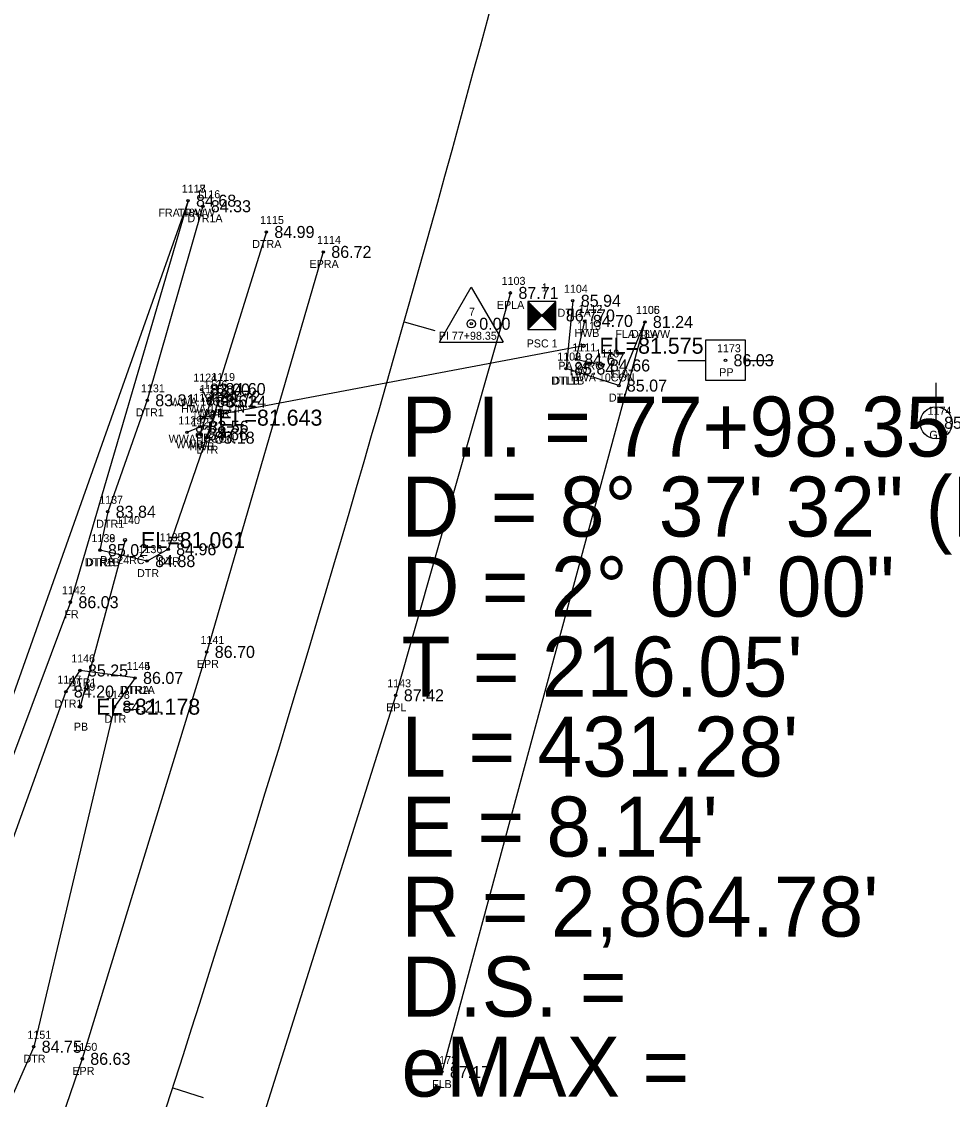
# Model space of a CAD drawing. Extents: x 2139392 to 2143384, y 505395 to 510520.
# Drawn here: x 2141351.5 to 2141467.9, y 510187.6 to 510322.4 of the extents above; entities that cross this region are included whole.
import ezdxf

# ---------------------------------------------------------------- set-up
doc = ezdxf.new("R2010")
doc.units = 0
for name, color, linetype in [('RD_EX_Bridge', 7, 'Continuous'), ('RD_EX_Bridge_txCode', 7, 'Continuous'), ('RD_EX_DR_Pipe', 7, 'Continuous'), ('RD_EX_DR_Pipe_txCode', 7, 'Continuous'), ('RD_EX_Fence_Other', 7, 'Continuous'), ('RD_EX_Fence_Other_txCode', 7, 'Continuous'), ('RD_EX_H2O', 7, 'Continuous'), ('RD_EX_H2O_txCode', 7, 'Continuous'), ('RD_EX_Road', 7, 'Continuous'), ('RD_EX_Road_txCode', 7, 'Continuous'), ('RD_EX_TX_Bridge_ELEV', 7, 'Continuous'), ('RD_EX_TX_Fence_Other_ELEV', 7, 'Continuous'), ('RD_EX_TX_H2O_ELEV', 7, 'Continuous'), ('RD_EX_TX_Road_ELEV', 7, 'Continuous'), ('RD_EX_TX_UT_ELEV', 7, 'Continuous'), ('RD_EX_TX_VEG_ELEV', 7, 'Continuous'), ('RD_EX_UT', 7, 'Continuous'), ('RD_EX_UT_txCode', 7, 'Continuous'), ('RD_EX_VEG', 7, 'Continuous'), ('RD_EX_VEG_txCode', 7, 'Continuous'), ('RD_HC_Cl', 7, 'Continuous'), ('RD_HC_Data', 7, 'Continuous'), ('RD_HC_Data_Tic', 7, 'Continuous'), ('RD_HC_Survey', 7, 'Continuous'), ('RD_HC_Survey_ELEV', 7, 'Continuous'), ('RD_HC_txCode', 7, 'Continuous'), ('RD_SMD_Locator', 7, 'Continuous'), ('RD_TX_Pipe_ElevEX', 7, 'Continuous')]:
    doc.layers.add(name, color=color, linetype=linetype)

msp = doc.modelspace()

# ---------------------------------------------------------------- linework, layer by layer
at = {"layer": 'RD_EX_Bridge'}
for p, q in [((2141374.04, 510276.37), (2141374.82, 510274.93)), ((2141375.34, 510275.48), (2141373.79, 510270.78)), ((2141373.87, 510271.73), (2141372.18, 510271.02))]:
    msp.add_line(p, q, dxfattribs=at)
msp.add_lwpolyline([(2141424.06, 510279.39), (2141420.85, 510280.14), (2141421.91, 510284.95)], dxfattribs=at)
at = {"layer": 'RD_EX_DR_Pipe'}
for p, q in [((2141421.74, 510281.85), (2141374.1, 510272.86)), ((2141364.45, 510257.56), (2141358.83, 510236.74))]:
    msp.add_line(p, q, dxfattribs=at)
at = {"layer": 'RD_EX_Fence_Other'}
msp.add_line((2141429.42, 510284.83), (2141404.04, 510191.07), dxfattribs=at)
msp.add_lwpolyline([(2141372.32, 510299.98), (2141357.62, 510249.8), (2141299.84, 510095.47), (2141291.7, 510075.55), (2141249.56, 510057.46), (2141172.32, 510090.13)], dxfattribs=at)
at = {"layer": 'RD_EX_H2O'}
msp.add_line((2141420.41, 510287.47), (2141419.58, 510279), dxfattribs=at)
for points in [[(2141374.17, 510299.29), (2141367.22, 510275.03), (2141362.28, 510261.1), (2141361.31, 510256.3)], [(2141382.11, 510296.07), (2141376, 510276.44), (2141376.07, 510274.88), (2141374.63, 510270.36), (2141369.84, 510256.41), (2141367.21, 510254.93), (2141361.31, 510256.3)], [(2141429.42, 510284.83), (2141426.17, 510276.87), (2141419.58, 510279)], [(2141365.7, 510240.33), (2141358.81, 510241.26), (2141357.05, 510238.63), (2141342.24, 510197.62), (2141327.87, 510160.27)], [(2141365.7, 510240.33), (2141363.12, 510236.72), (2141353.03, 510194.23), (2141336.56, 510156.75), (2141327.87, 510160.27)]]:
    msp.add_lwpolyline(points, dxfattribs=at)
at = {"layer": 'RD_EX_Road'}
for points in [[(2141389.23, 510293.58), (2141374.66, 510243.58), (2141359.1, 510192.72), (2141341.17, 510140.58), (2141322.74, 510087.97), (2141303.61, 510035.12), (2141287.18, 509990.16), (2141276.99, 509962.02), (2141248.91, 509884.35), (2141213.37, 509787.47), (2141207.76, 509772.94), (2141199.35, 509749.36), (2141191.47, 509727.8), (2141175.93, 509686.04), (2141140.09, 509588.3), (2141106.08, 509494.11), (2141096.82, 509469.24), (2141063.82, 509378.98), (2141052.52, 509348.48), (2141043.48, 509323.88)], [(2141412.62, 510288.46), (2141398.29, 510238.16), (2141381.65, 510185.39), (2141379.05, 510176.51), (2141367.08, 510141.57), (2141363.58, 510131.95), (2141345.23, 510080.36), (2141326.05, 510027.03), (2141308.64, 509979.4), (2141271.24, 509876.37), (2141240, 509789.51), (2141233.78, 509773.43), (2141223.56, 509746.41), (2141212.18, 509714.93), (2141204.36, 509694.36), (2141197.99, 509676.56), (2141193.66, 509664.6), (2141161.61, 509577.24), (2141123.75, 509473.61), (2141115.5, 509450.65), (2141102.09, 509414.61), (2141086.27, 509371.27), (2141050.42, 509272.83)]]:
    msp.add_lwpolyline(points, dxfattribs=at)
at = {"layer": 'RD_EX_UT'}
for p, q in [((2141441.99, 510282.55), (2141436.99, 510282.55)), ((2141436.99, 510282.55), (2141436.99, 510277.55)), ((2141441.99, 510277.55), (2141441.99, 510282.55)), ((2141433.56, 510279.99), (2141437.03, 510279.99)), ((2141441.92, 510279.99), (2141445.56, 510279.99)), ((2141436.99, 510277.55), (2141441.99, 510277.55)), ((2141465.82, 510272.22), (2141465.82, 510277.22))]:
    msp.add_line(p, q, dxfattribs=at)
msp.add_circle((2141465.82, 510272.22), 2, dxfattribs=at)
at = {"layer": 'RD_EX_VEG'}
msp.add_lwpolyline([(2141372.32, 510299.98), (2141299.84, 510095.47), (2141264.54, 510000.34)], dxfattribs=at)
at = {"layer": 'RD_HC_Cl'}
msp.add_arc((2138642.96, 511065.46), 2864.78, 339.91581, 348.5415, dxfattribs=at)
at = {"layer": 'RD_HC_Data'}
for p, q in [((2141403.75, 510282.31), (2141407.72, 510289.19)), ((2141407.72, 510289.19), (2141411.69, 510282.31)), ((2141403.75, 510282.31), (2141411.69, 510282.31))]:
    msp.add_line(p, q, dxfattribs=at)
msp.add_circle((2141407.72, 510284.6), 0.529, dxfattribs=at)
at = {"layer": 'RD_HC_Data_Tic'}
for p, q in [((2141399.33, 510284.83), (2141403.18, 510283.74)), ((2141370.41, 510189.11), (2141374.22, 510187.89))]:
    msp.add_line(p, q, dxfattribs=at)
at = {"layer": 'RD_HC_Survey'}
for p, q in [((2141414.79, 510287.39), (2141418.29, 510283.89)), ((2141418.29, 510287.39), (2141414.79, 510283.89)), ((2141414.81, 510287.36), (2141414.81, 510283.91)), ((2141414.84, 510287.34), (2141414.84, 510283.94)), ((2141414.86, 510287.31), (2141414.86, 510283.96)), ((2141414.89, 510287.29), (2141414.89, 510283.99)), ((2141414.91, 510287.26), (2141414.91, 510284.01)), ((2141414.94, 510287.24), (2141414.94, 510284.04)), ((2141414.96, 510287.21), (2141414.96, 510284.06)), ((2141414.99, 510287.19), (2141414.99, 510284.09)), ((2141415.01, 510287.16), (2141415.01, 510284.11)), ((2141415.03, 510287.14), (2141415.03, 510284.14)), ((2141415.06, 510287.12), (2141415.06, 510284.16)), ((2141415.08, 510287.09), (2141415.08, 510284.18)), ((2141415.11, 510287.07), (2141415.11, 510284.21)), ((2141415.13, 510287.04), (2141415.13, 510284.23)), ((2141415.16, 510287.02), (2141415.16, 510284.26)), ((2141415.18, 510286.99), (2141415.18, 510284.28)), ((2141415.21, 510286.97), (2141415.21, 510284.31)), ((2141415.23, 510286.94), (2141415.23, 510284.33)), ((2141415.26, 510286.92), (2141415.26, 510284.36)), ((2141415.28, 510286.89), (2141415.28, 510284.38)), ((2141415.31, 510286.87), (2141415.31, 510284.41)), ((2141415.33, 510286.84), (2141415.33, 510284.43)), ((2141415.36, 510286.82), (2141415.36, 510284.46)), ((2141415.38, 510286.79), (2141415.38, 510284.48)), ((2141415.41, 510286.77), (2141415.41, 510284.51)), ((2141415.43, 510286.74), (2141415.43, 510284.53)), ((2141415.46, 510286.72), (2141415.46, 510284.56)), ((2141415.48, 510286.69), (2141415.48, 510284.58)), ((2141415.5, 510286.67), (2141415.5, 510284.61)), ((2141415.53, 510286.65), (2141415.53, 510284.63)), ((2141417.54, 510286.65), (2141417.54, 510284.63)), ((2141417.57, 510286.67), (2141417.57, 510284.61)), ((2141417.59, 510286.69), (2141417.59, 510284.58)), ((2141417.62, 510286.72), (2141417.62, 510284.56)), ((2141417.64, 510286.74), (2141417.64, 510284.53)), ((2141417.67, 510286.77), (2141417.67, 510284.51)), ((2141417.69, 510286.79), (2141417.69, 510284.48)), ((2141417.72, 510286.82), (2141417.72, 510284.46)), ((2141417.74, 510286.84), (2141417.74, 510284.43)), ((2141417.77, 510286.87), (2141417.77, 510284.41)), ((2141417.79, 510286.89), (2141417.79, 510284.38)), ((2141417.82, 510286.92), (2141417.82, 510284.36)), ((2141417.84, 510286.94), (2141417.84, 510284.33)), ((2141417.87, 510286.97), (2141417.87, 510284.31)), ((2141417.89, 510286.99), (2141417.89, 510284.28)), ((2141417.92, 510287.02), (2141417.92, 510284.26)), ((2141417.94, 510287.04), (2141417.94, 510284.23)), ((2141417.97, 510287.07), (2141417.97, 510284.21)), ((2141417.99, 510287.09), (2141417.99, 510284.18)), ((2141418.01, 510287.12), (2141418.01, 510284.16)), ((2141418.04, 510287.14), (2141418.04, 510284.14)), ((2141418.06, 510287.16), (2141418.06, 510284.11)), ((2141418.09, 510287.19), (2141418.09, 510284.09)), ((2141418.11, 510287.21), (2141418.11, 510284.06)), ((2141418.14, 510287.24), (2141418.14, 510284.04)), ((2141418.16, 510287.26), (2141418.16, 510284.01)), ((2141418.19, 510287.29), (2141418.19, 510283.99)), ((2141418.21, 510287.31), (2141418.21, 510283.96)), ((2141418.24, 510287.34), (2141418.24, 510283.94)), ((2141418.26, 510287.36), (2141418.26, 510283.91)), ((2141415.55, 510286.62), (2141415.55, 510284.65)), ((2141415.58, 510286.6), (2141415.58, 510284.68)), ((2141415.6, 510286.57), (2141415.6, 510284.7)), ((2141415.63, 510286.55), (2141415.63, 510284.73)), ((2141415.65, 510286.52), (2141415.65, 510284.75)), ((2141415.68, 510286.5), (2141415.68, 510284.78)), ((2141415.7, 510286.47), (2141415.7, 510284.8)), ((2141415.73, 510286.45), (2141415.73, 510284.83)), ((2141415.75, 510286.42), (2141415.75, 510284.85)), ((2141415.78, 510286.4), (2141415.78, 510284.88)), ((2141415.8, 510286.37), (2141415.8, 510284.9)), ((2141415.83, 510286.35), (2141415.83, 510284.93)), ((2141415.85, 510286.32), (2141415.85, 510284.95)), ((2141415.88, 510286.3), (2141415.88, 510284.98)), ((2141415.9, 510286.27), (2141415.9, 510285)), ((2141415.93, 510286.25), (2141415.93, 510285.03)), ((2141415.95, 510286.22), (2141415.95, 510285.05)), ((2141415.98, 510286.2), (2141415.98, 510285.08)), ((2141416, 510286.17), (2141416, 510285.1)), ((2141416.02, 510286.15), (2141416.02, 510285.13)), ((2141416.05, 510286.13), (2141416.05, 510285.15)), ((2141416.07, 510286.1), (2141416.07, 510285.17)), ((2141416.1, 510286.08), (2141416.1, 510285.2)), ((2141416.12, 510286.05), (2141416.12, 510285.22)), ((2141416.15, 510286.03), (2141416.15, 510285.25)), ((2141416.17, 510286), (2141416.17, 510285.27)), ((2141416.2, 510285.98), (2141416.2, 510285.3)), ((2141416.22, 510285.95), (2141416.22, 510285.32)), ((2141416.25, 510285.93), (2141416.25, 510285.35)), ((2141416.27, 510285.9), (2141416.27, 510285.37)), ((2141416.3, 510285.88), (2141416.3, 510285.4)), ((2141416.32, 510285.85), (2141416.32, 510285.42)), ((2141416.35, 510285.83), (2141416.35, 510285.45)), ((2141416.37, 510285.8), (2141416.37, 510285.47)), ((2141416.4, 510285.78), (2141416.4, 510285.5)), ((2141416.42, 510285.75), (2141416.42, 510285.52)), ((2141416.45, 510285.73), (2141416.45, 510285.55)), ((2141416.47, 510285.7), (2141416.47, 510285.57)), ((2141416.49, 510285.68), (2141416.49, 510285.6)), ((2141416.52, 510285.66), (2141416.52, 510285.62)), ((2141416.55, 510285.66), (2141416.55, 510285.62)), ((2141416.58, 510285.68), (2141416.58, 510285.6)), ((2141416.6, 510285.7), (2141416.6, 510285.57)), ((2141416.63, 510285.73), (2141416.63, 510285.55)), ((2141416.65, 510285.75), (2141416.65, 510285.52)), ((2141416.68, 510285.78), (2141416.68, 510285.5)), ((2141416.7, 510285.8), (2141416.7, 510285.47)), ((2141416.73, 510285.83), (2141416.73, 510285.45)), ((2141416.75, 510285.85), (2141416.75, 510285.42)), ((2141416.78, 510285.88), (2141416.78, 510285.4)), ((2141416.8, 510285.9), (2141416.8, 510285.37)), ((2141416.83, 510285.93), (2141416.83, 510285.35)), ((2141416.85, 510285.95), (2141416.85, 510285.32)), ((2141416.88, 510285.98), (2141416.88, 510285.3)), ((2141416.9, 510286), (2141416.9, 510285.27)), ((2141416.93, 510286.03), (2141416.93, 510285.25)), ((2141416.95, 510286.05), (2141416.95, 510285.22)), ((2141416.98, 510286.08), (2141416.98, 510285.2)), ((2141417, 510286.1), (2141417, 510285.17)), ((2141417.02, 510286.13), (2141417.02, 510285.15)), ((2141417.05, 510286.15), (2141417.05, 510285.13)), ((2141417.07, 510286.17), (2141417.07, 510285.1)), ((2141417.1, 510286.2), (2141417.1, 510285.08)), ((2141417.12, 510286.22), (2141417.12, 510285.05)), ((2141417.15, 510286.25), (2141417.15, 510285.03)), ((2141417.17, 510286.27), (2141417.17, 510285)), ((2141417.2, 510286.3), (2141417.2, 510284.98)), ((2141417.22, 510286.32), (2141417.22, 510284.95)), ((2141417.25, 510286.35), (2141417.25, 510284.93)), ((2141417.27, 510286.37), (2141417.27, 510284.9)), ((2141417.3, 510286.4), (2141417.3, 510284.88)), ((2141417.32, 510286.42), (2141417.32, 510284.85)), ((2141417.35, 510286.45), (2141417.35, 510284.83)), ((2141417.37, 510286.47), (2141417.37, 510284.8)), ((2141417.4, 510286.5), (2141417.4, 510284.78)), ((2141417.42, 510286.52), (2141417.42, 510284.75)), ((2141417.45, 510286.55), (2141417.45, 510284.73)), ((2141417.47, 510286.57), (2141417.47, 510284.7)), ((2141417.5, 510286.6), (2141417.5, 510284.68)), ((2141417.52, 510286.62), (2141417.52, 510284.65))]:
    msp.add_line(p, q, dxfattribs=at)
msp.add_lwpolyline([(2141418.29, 510287.39), (2141414.79, 510287.39), (2141414.79, 510283.89), (2141418.29, 510283.89)], close=True, dxfattribs=at)
at = {"layer": 'RD_SMD_Locator'}
for centre, radius in [((2141372.32, 510299.98), 0.15), ((2141372.32, 510299.98), 0.15), ((2141374.17, 510299.29), 0.15), ((2141382.11, 510296.07), 0.15), ((2141389.23, 510293.58), 0.15), ((2141412.62, 510288.46), 0.15), ((2141420.41, 510287.47), 0.15), ((2141416.54, 510285.64), 0.15), ((2141407.72, 510284.6), 0.15), ((2141421.91, 510284.95), 0.15), ((2141429.42, 510284.83), 0.15), ((2141429.42, 510284.83), 0.15), ((2141421.74, 510281.85), 0.2), ((2141420.85, 510280.14), 0.15), ((2141439.5, 510280.04), 0.15), ((2141419.58, 510279), 0.15), ((2141419.58, 510279), 0.15), ((2141424.06, 510279.39), 0.15), ((2141374.04, 510276.37), 0.15), ((2141376, 510276.44), 0.15), ((2141426.17, 510276.87), 0.15), ((2141367.22, 510275.03), 0.15), ((2141374.82, 510274.93), 0.15), ((2141375.34, 510275.48), 0.15), ((2141376.07, 510274.88), 0.15), ((2141373.87, 510271.73), 0.15), ((2141374.1, 510272.86), 0.2), ((2141465.82, 510272.22), 0.15), ((2141372.18, 510271.02), 0.15), ((2141373.79, 510270.78), 0.15), ((2141374.63, 510270.36), 0.15), ((2141362.28, 510261.1), 0.15), ((2141364.45, 510257.56), 0.2), ((2141361.31, 510256.3), 0.15), ((2141361.31, 510256.3), 0.15), ((2141369.84, 510256.41), 0.15), ((2141367.21, 510254.93), 0.15), ((2141357.62, 510249.8), 0.15), ((2141374.66, 510243.58), 0.15), ((2141358.81, 510241.26), 0.15), ((2141365.7, 510240.33), 0.15), ((2141365.7, 510240.33), 0.15), ((2141357.05, 510238.63), 0.15), ((2141398.29, 510238.16), 0.15), ((2141358.83, 510236.74), 0.2), ((2141363.12, 510236.72), 0.15), ((2141353.03, 510194.23), 0.15), ((2141359.1, 510192.72), 0.15), ((2141404.04, 510191.07), 0.15)]:
    msp.add_circle(centre, radius, dxfattribs=at)

# ---------------------------------------------------------------- texts
at = {"layer": 'RD_EX_Bridge_txCode'}
for s, p in [('1112', (2141421.13, 510285.95)), ('HWB', (2141420.62, 510282.95)), ('1111', (2141420.36, 510281.14)), ('1110', (2141423.24, 510280.39)), ('HW', (2141420.03, 510278.14)), ('1124', (2141372.98, 510277.37)), ('1126', (2141374.26, 510276.48)), ('HWA 10CON', (2141420.18, 510277.39)), ('1125', (2141373.76, 510275.93)), ('WWA 10CON', (2141370.08, 510274.37)), ('HWA 10CON', (2141371.46, 510273.48)), ('1128', (2141372.8, 510272.73)), ('WWB', (2141373.45, 510272.93)), ('1129', (2141371.11, 510272.02)), ('1127', (2141372.72, 510271.78)), ('WWA 10CON', (2141369.9, 510269.73)), ('WWB', (2141370.8, 510269.02)), ('HWB', (2141372.5, 510268.78))]:
    msp.add_text(s, height=1, dxfattribs=at).set_placement(p)
at = {"layer": 'RD_EX_DR_Pipe_txCode'}
for s, p in [('1113', (2141420.96, 510283.85)), ('PA 24RC', (2141418.61, 510278.85)), ('1130', (2141373, 510274.86)), ('PB', (2141373.32, 510269.86)), ('1140', (2141363.34, 510259.56)), ('PA 24RC', (2141361.32, 510254.56)), ('1149', (2141357.76, 510238.74)), ('PB', (2141358.05, 510233.74))]:
    msp.add_text(s, height=1, dxfattribs=at).set_placement(p)
at = {"layer": 'RD_EX_Fence_Other_txCode'}
for s, p in [('1117', (2141371.54, 510300.98)), ('FRA 48WW', (2141368.62, 510297.98)), ('1106', (2141428.3, 510285.83)), ('FLA 48WW', (2141425.74, 510282.83)), ('1142', (2141356.56, 510250.8)), ('FR', (2141356.87, 510247.8)), ('1172', (2141402.97, 510192.07)), ('FLB', (2141402.83, 510189.07))]:
    msp.add_text(s, height=1, dxfattribs=at).set_placement(p)
at = {"layer": 'RD_EX_H2O_txCode'}
for s, p in [('1116', (2141373.37, 510300.29)), ('DTR1A', (2141372.25, 510297.29)), ('1115', (2141381.33, 510297.07)), ('DTRA', (2141380.35, 510294.07)), ('1104', (2141419.31, 510288.47)), ('1105', (2141428.32, 510285.83)), ('DTL1A', (2141418.51, 510285.47)), ('DTLA', (2141427.69, 510282.83)), ('1108', (2141418.47, 510280)), ('1109', (2141418.47, 510280)), ('1107', (2141425.07, 510277.87)), ('1119', (2141375.22, 510277.44)), ('DTL1B', (2141417.7, 510277)), ('DTLB', (2141417.86, 510277)), ('1131', (2141366.44, 510276.03)), ('1120', (2141374.96, 510275.88)), ('DTL', (2141424.93, 510274.87)), ('DTR', (2141374.73, 510274.44)), ('DTR1', (2141365.79, 510273.03)), ('DTR', (2141374.8, 510272.88)), ('1121', (2141373.85, 510271.36)), ('DTR', (2141373.36, 510268.36)), ('1137', (2141361.22, 510262.1)), ('DTR1', (2141360.85, 510259.1)), ('1135', (2141368.78, 510257.41)), ('1138', (2141360.25, 510257.3)), ('1139', (2141360.25, 510257.3)), ('1136', (2141366.13, 510255.93)), ('DTR1B', (2141359.41, 510254.3)), ('DTRB', (2141359.57, 510254.3)), ('DTR', (2141368.57, 510254.41)), ('DTR', (2141365.95, 510252.93)), ('1146', (2141357.72, 510242.26)), ('1144', (2141364.64, 510241.33)), ('1145', (2141364.64, 510241.33)), ('1147', (2141355.99, 510239.63)), ('DTR1', (2141357.37, 510239.26)), ('1148', (2141362.06, 510237.72)), ('DTR1A', (2141363.78, 510238.33)), ('DTRA', (2141363.94, 510238.33)), ('DTR1', (2141355.62, 510236.63)), ('DTR', (2141361.86, 510234.72)), ('1151', (2141352.25, 510195.23)), ('DTR', (2141351.76, 510192.23))]:
    msp.add_text(s, height=1, dxfattribs=at).set_placement(p)
at = {"layer": 'RD_EX_Road_txCode'}
for s, p in [('1114', (2141388.45, 510294.58)), ('EPRA', (2141387.51, 510291.58)), ('1103', (2141411.52, 510289.46)), ('EPLA', (2141410.93, 510286.46)), ('1141', (2141373.88, 510244.58)), ('EPR', (2141373.43, 510241.58)), ('1143', (2141397.22, 510239.16)), ('EPL', (2141397.08, 510236.16)), ('1150', (2141358, 510193.72)), ('EPR', (2141357.87, 510190.72))]:
    msp.add_text(s, height=1, dxfattribs=at).set_placement(p)
at = {"layer": 'RD_EX_TX_Bridge_ELEV'}
for s, p in [('84.70', (2141422.91, 510284.2)), ('84.67', (2141421.85, 510279.39)), ('84.66', (2141425.06, 510278.64)), ('83.00', (2141375.04, 510275.62)), ('84.72', (2141376.34, 510274.73)), ('83.61', (2141375.82, 510274.18)), ('83.56', (2141374.87, 510270.98)), ('82.97', (2141373.18, 510270.27)), ('84.66', (2141374.79, 510270.03))]:
    msp.add_text(s, height=1.5, dxfattribs=at).set_placement(p)
at = {"layer": 'RD_EX_TX_Fence_Other_ELEV'}
for s, p in [('84.68', (2141373.32, 510299.23)), ('81.24', (2141430.42, 510284.08)), ('86.03', (2141358.62, 510249.05)), ('87.17', (2141405.04, 510190.32))]:
    msp.add_text(s, height=1.5, dxfattribs=at).set_placement(p)
at = {"layer": 'RD_EX_TX_H2O_ELEV'}
for s, p in [('84.33', (2141375.17, 510298.54)), ('84.99', (2141383.11, 510295.32)), ('85.94', (2141421.41, 510286.72)), ('81.24', (2141430.42, 510284.08)), ('85.84', (2141420.58, 510278.25)), ('85.84', (2141420.58, 510278.25)), ('84.60', (2141377, 510275.69)), ('85.07', (2141427.17, 510276.12)), ('83.31', (2141368.22, 510274.28)), ('85.24', (2141377.07, 510274.13)), ('85.18', (2141375.63, 510269.61)), ('83.84', (2141363.28, 510260.35)), ('85.02', (2141362.31, 510255.55)), ('85.02', (2141362.31, 510255.55)), ('84.96', (2141370.84, 510255.66)), ('84.88', (2141368.21, 510254.18)), ('85.25', (2141359.81, 510240.51)), ('86.07', (2141366.7, 510239.58)), ('86.07', (2141366.7, 510239.58)), ('84.20', (2141358.05, 510237.88)), ('84.21', (2141364.12, 510235.97)), ('84.75', (2141354.03, 510193.48))]:
    msp.add_text(s, height=1.5, dxfattribs=at).set_placement(p)
at = {"layer": 'RD_EX_TX_Road_ELEV'}
for s, p in [('86.72', (2141390.23, 510292.83)), ('87.71', (2141413.62, 510287.71)), ('86.70', (2141375.66, 510242.83)), ('87.42', (2141399.29, 510237.41)), ('86.63', (2141360.1, 510191.97))]:
    msp.add_text(s, height=1.5, dxfattribs=at).set_placement(p)
at = {"layer": 'RD_EX_TX_UT_ELEV'}
msp.add_text('85.65', height=1.5, dxfattribs=at).set_placement((2141466.82, 510271.47))
at = {"layer": 'RD_EX_TX_VEG_ELEV'}
msp.add_text('84.68', height=1.5, dxfattribs=at).set_placement((2141373.32, 510299.23))
at = {"layer": 'RD_EX_UT_txCode'}
for s, p in [('1173', (2141438.44, 510281.04)), ('PP', (2141438.72, 510278.04)), ('1174', (2141464.76, 510273.22)), ('GW', (2141464.98, 510270.22))]:
    msp.add_text(s, height=1, dxfattribs=at).set_placement(p)
at = {"layer": 'RD_EX_VEG_txCode'}
for s, p in [('1118', (2141371.54, 510300.98)), ('TRA', (2141371.04, 510297.98))]:
    msp.add_text(s, height=1, dxfattribs=at).set_placement(p)
at = {"layer": 'RD_HC_Data'}
for s, p in [('P.I. = 77+98.35', (2141399, 510268)), ('D', (2141399, 510258)), ('    = 8%%d 37\' 32" (RT)', (2141399, 510258)), ('D = 2%%d 00\' 00"', (2141399, 510248)), ("T = 216.05'", (2141399, 510238)), ("L = 431.28'", (2141399, 510228)), ("E = 8.14'", (2141399, 510218)), ("R = 2,864.78'", (2141399, 510208)), ('D.S. = ', (2141399, 510198)), ('eMAX = ', (2141399, 510188))]:
    msp.add_text(s, height=7.5, dxfattribs=at).set_placement(p)
at = {"layer": 'RD_HC_Survey_ELEV'}
for s, p in [('0.00', (2141408.72, 510283.85)), ('86.770', (2141419.54, 510284.89)), ('86.03', (2141440.5, 510279.29))]:
    msp.add_text(s, height=1.5, dxfattribs=at).set_placement(p)
at = {"layer": 'RD_HC_txCode'}
for s, p in [('1', (2141416.54, 510288.64)), ('7', (2141407.44, 510285.6)), ('PI 77+98.35', (2141403.66, 510282.6)), ('PSC 1', (2141414.65, 510281.64))]:
    msp.add_text(s, height=1, dxfattribs=at).set_placement(p)
at = {"layer": 'RD_TX_Pipe_ElevEX'}
for s, p in [('EL=81.575', (2141423.74, 510280.85)), ('EL=81.643', (2141376.1, 510271.86)), ('EL=81.061', (2141366.45, 510256.56)), ('EL=81.178', (2141360.83, 510235.74))]:
    msp.add_text(s, height=2, dxfattribs=at).set_placement(p)

doc.saveas('drawing.dxf')
